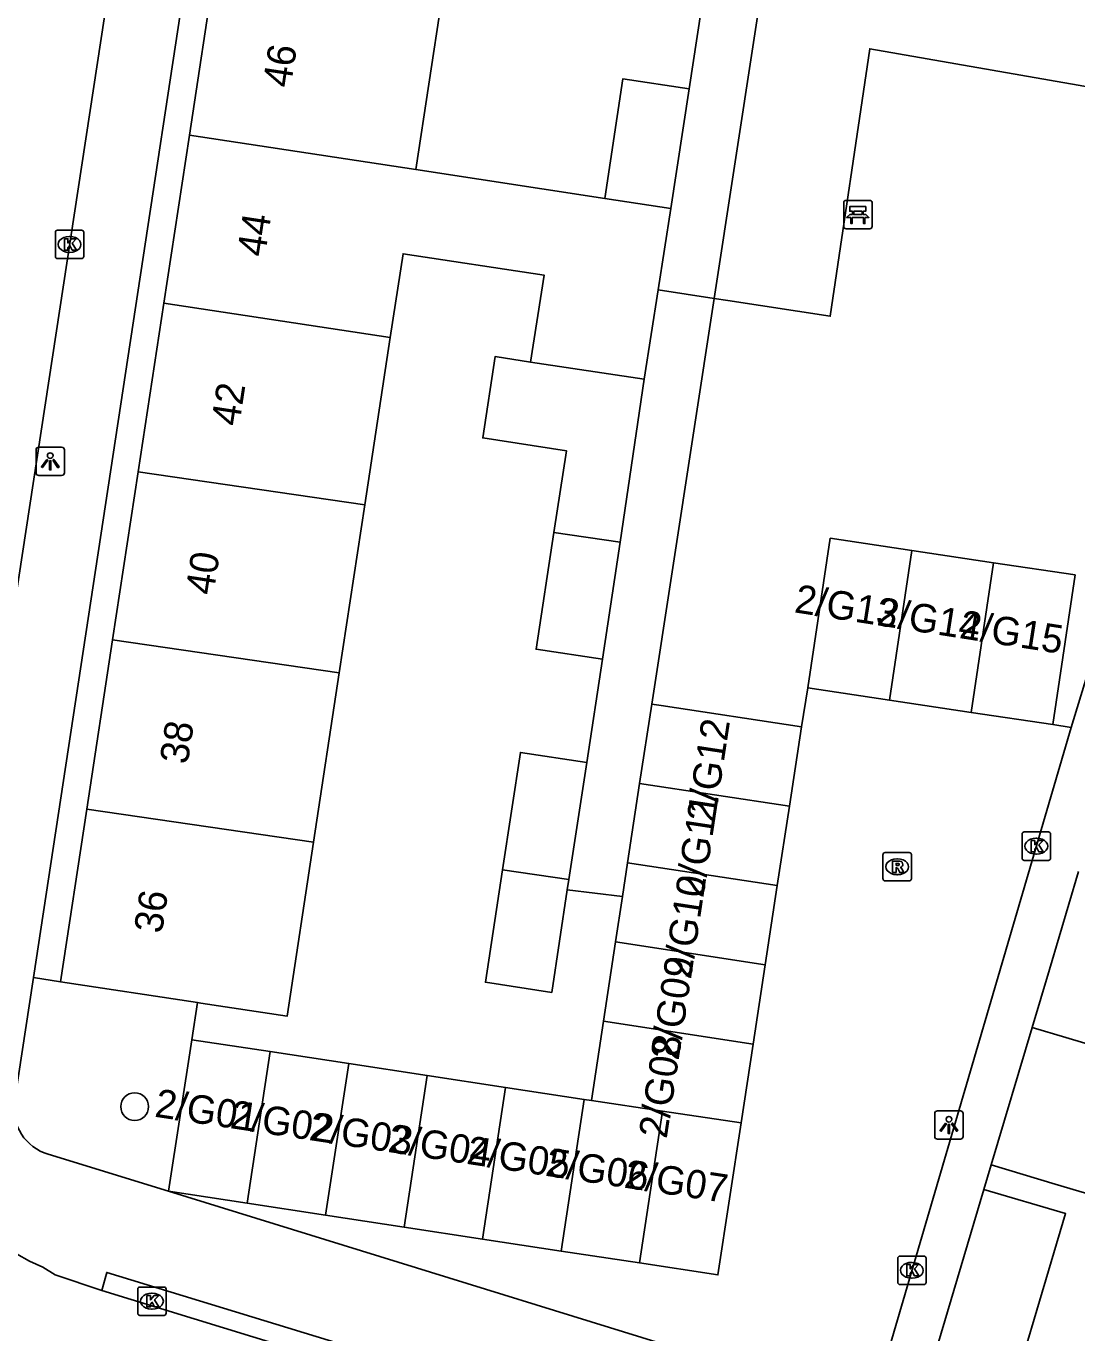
# Model space of a CAD drawing. Extents: x 161084 to 161928, y 385355 to 386522.
# Drawn here: x 161749.15 to 161786.17, y 385534.98 to 385581.01 of the extents above; entities that cross this region are included whole.
import ezdxf

# ---------------------------------------------------------------- set-up
doc = ezdxf.new("R2010")
doc.units = 0
for name, color, linetype in [('IMGEO_Bank', 7, 'Continuous'), ('IMGEO_Boom', 7, 'Continuous'), ('IMGEO_Groenvoorziening', 7, 'Continuous'), ('IMGEO_Kolk', 7, 'Continuous'), ('IMGEO_Lichtpunt', 7, 'Continuous'), ('IMGEO_Pand', 7, 'Continuous'), ('IMGEO_Pand_nummerreeks', 7, 'Continuous'), ('IMGEO_Rijbaan_lokaal_open', 7, 'Continuous'), ('IMGEO_Rioolput', 7, 'Continuous'), ('IMGEO_Voetpad_open', 7, 'Continuous')]:
    doc.layers.add(name, color=color, linetype=linetype)

msp = doc.modelspace()

# ---------------------------------------------------------------- linework, layer by layer
at = {"layer": 'IMGEO_Bank'}
for p, q in [((161777.952, 385573.949), (161777.952, 385574.79)), ((161777.952, 385574.79), (161777.952, 385573.949)), ((161778.027, 385574.874), (161778.868, 385574.874)), ((161778.868, 385574.874), (161778.027, 385574.874)), ((161778.952, 385574.799), (161778.952, 385573.958)), ((161778.952, 385573.958), (161778.952, 385574.799)), ((161778.649, 385574.272), (161778.256, 385574.272)), ((161778.261, 385574.38), (161778.261, 385574.486)), ((161778.305, 385574.486), (161778.305, 385574.38)), ((161778.593, 385574.492), (161778.311, 385574.492)), ((161778.311, 385574.374), (161778.593, 385574.374)), ((161778.599, 385574.38), (161778.599, 385574.486)), ((161778.643, 385574.486), (161778.643, 385574.38)), ((161778.877, 385573.874), (161778.036, 385573.874)), ((161778.036, 385573.874), (161778.877, 385573.874))]:
    msp.add_line(p, q, dxfattribs=at)
for points in [[(161778.255, 385574.492), (161778.169, 385574.492), (161778.169, 385574.653), (161778.732, 385574.653), (161778.732, 385574.492), (161778.649, 385574.492)], [(161778.199, 385574.272), (161778.057, 385574.272), (161778.169, 385574.374), (161778.255, 385574.374)], [(161778.249, 385574.265), (161778.249, 385574.058), (161778.206, 385574.058), (161778.206, 385574.265)], [(161778.649, 385574.374), (161778.732, 385574.374), (161778.844, 385574.272), (161778.705, 385574.272)], [(161778.699, 385574.265), (161778.699, 385574.058), (161778.655, 385574.058), (161778.655, 385574.265)]]:
    msp.add_lwpolyline(points, dxfattribs=at)
for centre, radius, start, end in [((161778.03, 385574.796), 0.0779, 92.4484, 184.2845), ((161778.03, 385574.796), 0.0779, 92.4484, 184.2845), ((161778.874, 385574.796), 0.0779, 2.4484, 94.2845), ((161778.874, 385574.796), 0.0779, 2.4484, 94.2845), ((161778.199, 385574.265), 0.00671, 2.8957, 87.1043), ((161778.256, 385574.265), 0.00671, 92.8957, 177.1043), ((161778.254, 385574.485), 0.00671, 2.8957, 87.1043), ((161778.254, 385574.381), 0.00671, 272.8957, 357.1043), ((161778.311, 385574.485), 0.00671, 92.8957, 177.1043), ((161778.311, 385574.381), 0.00671, 182.8957, 267.1043), ((161778.593, 385574.485), 0.00671, 2.8957, 87.1043), ((161778.593, 385574.381), 0.00671, 272.8957, 357.1043), ((161778.65, 385574.485), 0.00671, 92.8957, 177.1043), ((161778.65, 385574.381), 0.00671, 182.8957, 267.1043), ((161778.648, 385574.265), 0.00671, 2.8957, 87.1043), ((161778.705, 385574.265), 0.00671, 92.8957, 177.1043), ((161778.03, 385573.952), 0.0779, 182.4484, 274.2845), ((161778.03, 385573.952), 0.0779, 182.4484, 274.2845), ((161778.874, 385573.952), 0.0779, 272.4484, 4.2845), ((161778.874, 385573.952), 0.0779, 272.4484, 4.2845)]:
    msp.add_arc(centre, radius, start, end, dxfattribs=at)
at = {"layer": 'IMGEO_Boom'}
msp.add_circle((161752.976, 385542.947), 0.489, dxfattribs=at)
at = {"layer": 'IMGEO_Groenvoorziening'}
for points in [[(161750.362, 385547.348), (161749.416, 385547.492)], [(161755.185, 385546.613), (161754.986, 385545.305)]]:
    msp.add_lwpolyline(points, dxfattribs=at)
at = {"layer": 'IMGEO_Kolk'}
for p, q in [((161750.182, 385572.897), (161750.182, 385573.749)), ((161750.257, 385573.823), (161751.109, 385573.823)), ((161751.183, 385573.749), (161751.183, 385572.897)), ((161750.67, 385573.603), (161750.695, 385573.603)), ((161751.109, 385572.823), (161750.257, 385572.823)), ((161750.693, 385573.043), (161750.668, 385573.043)), ((161784.238, 385551.696), (161784.238, 385552.548)), ((161784.313, 385552.622), (161785.165, 385552.622)), ((161785.239, 385552.548), (161785.239, 385551.696)), ((161784.726, 385552.402), (161784.751, 385552.402)), ((161785.165, 385551.622), (161784.313, 385551.622)), ((161784.749, 385551.842), (161784.724, 385551.842)), ((161779.855, 385536.753), (161779.855, 385537.605)), ((161779.93, 385537.679), (161780.782, 385537.679)), ((161780.343, 385537.459), (161780.368, 385537.459)), ((161780.856, 385537.605), (161780.856, 385536.753)), ((161780.366, 385536.899), (161780.341, 385536.899)), ((161753.085, 385535.664), (161753.085, 385536.516)), ((161753.16, 385536.59), (161754.012, 385536.59)), ((161753.573, 385536.37), (161753.598, 385536.37)), ((161754.086, 385536.516), (161754.086, 385535.664)), ((161780.782, 385536.679), (161779.93, 385536.679)), ((161754.012, 385535.59), (161753.16, 385535.59)), ((161753.596, 385535.81), (161753.571, 385535.81))]:
    msp.add_line(p, q, dxfattribs=at)
for points in [[(161750.182, 385572.897), (161750.182, 385573.749)], [(161750.257, 385573.823), (161751.109, 385573.823)], [(161751.183, 385573.749), (161751.183, 385572.897)], [(161750.503, 385573.523), (161750.626, 385573.523), (161750.626, 385573.372), (161750.756, 385573.523), (161750.92, 385573.523), (161750.774, 385573.372), (161750.927, 385573.123), (161750.775, 385573.123), (161750.69, 385573.287), (161750.626, 385573.22), (161750.626, 385573.123), (161750.503, 385573.123), (161750.503, 385573.523)], [(161751.109, 385572.823), (161750.257, 385572.823)], [(161784.238, 385551.696), (161784.238, 385552.548)], [(161784.313, 385552.622), (161785.165, 385552.622)], [(161785.239, 385552.548), (161785.239, 385551.696)], [(161784.559, 385552.322), (161784.682, 385552.322), (161784.682, 385552.171), (161784.812, 385552.322), (161784.976, 385552.322), (161784.83, 385552.171), (161784.983, 385551.922), (161784.831, 385551.922), (161784.746, 385552.086), (161784.682, 385552.019), (161784.682, 385551.922), (161784.559, 385551.922), (161784.559, 385552.322)], [(161785.165, 385551.622), (161784.313, 385551.622)], [(161779.855, 385536.753), (161779.855, 385537.605)], [(161779.93, 385537.679), (161780.782, 385537.679)], [(161780.176, 385537.379), (161780.299, 385537.379), (161780.299, 385537.228), (161780.429, 385537.379), (161780.593, 385537.379), (161780.447, 385537.228), (161780.6, 385536.979), (161780.448, 385536.979), (161780.363, 385537.143), (161780.299, 385537.076), (161780.299, 385536.979), (161780.176, 385536.979), (161780.176, 385537.379)], [(161780.856, 385537.605), (161780.856, 385536.753)], [(161753.085, 385535.664), (161753.085, 385536.516)], [(161753.16, 385536.59), (161754.012, 385536.59)], [(161754.086, 385536.516), (161754.086, 385535.664)], [(161780.782, 385536.679), (161779.93, 385536.679)], [(161753.406, 385536.29), (161753.529, 385536.29), (161753.529, 385536.139), (161753.659, 385536.29), (161753.823, 385536.29), (161753.677, 385536.139), (161753.83, 385535.89), (161753.678, 385535.89), (161753.593, 385536.054), (161753.529, 385535.987), (161753.529, 385535.89), (161753.406, 385535.89), (161753.406, 385536.29)], [(161754.012, 385535.59), (161753.16, 385535.59)]]:
    msp.add_lwpolyline(points, dxfattribs=at)
for centre, start, end in [((161750.259, 385573.747), 91.552, 178.448), ((161750.259, 385573.747), 91.552, 178.448), ((161751.107, 385573.747), 1.552, 88.448), ((161751.107, 385573.747), 1.552, 88.448), ((161750.259, 385572.899), 181.552, 268.448), ((161750.259, 385572.899), 181.552, 268.448), ((161751.107, 385572.899), 271.552, 358.448), ((161751.107, 385572.899), 271.552, 358.448), ((161784.315, 385552.546), 91.552, 178.448), ((161784.315, 385552.546), 91.552, 178.448), ((161785.163, 385552.546), 1.552, 88.448), ((161785.163, 385552.546), 1.552, 88.448), ((161784.315, 385551.698), 181.552, 268.448), ((161784.315, 385551.698), 181.552, 268.448), ((161785.163, 385551.698), 271.552, 358.448), ((161785.163, 385551.698), 271.552, 358.448), ((161779.932, 385537.603), 91.552, 178.448), ((161779.932, 385537.603), 91.552, 178.448), ((161780.78, 385537.603), 1.552, 88.448), ((161780.78, 385537.603), 1.552, 88.448), ((161753.162, 385536.514), 91.552, 178.448), ((161753.162, 385536.514), 91.552, 178.448), ((161754.01, 385536.514), 1.552, 88.448), ((161754.01, 385536.514), 1.552, 88.448), ((161779.932, 385536.755), 181.552, 268.448), ((161779.932, 385536.755), 181.552, 268.448), ((161780.78, 385536.755), 271.552, 358.448), ((161780.78, 385536.755), 271.552, 358.448), ((161753.162, 385535.666), 181.552, 268.448), ((161753.162, 385535.666), 181.552, 268.448), ((161754.01, 385535.666), 271.552, 358.448), ((161754.01, 385535.666), 271.552, 358.448)]:
    msp.add_arc(centre, 0.0765, start, end, dxfattribs=at)
for centre, major_axis, ratio, start_param, end_param in [((161750.669, 385573.323), (-0.387, 0.002), 0.722429, 4.712389, 7.853982), ((161750.694, 385573.323), (-0.39, 0.002), 0.717154, 1.570796, 4.712389), ((161784.725, 385552.122), (-0.387, 0.002), 0.722429, 4.712389, 7.853982), ((161784.75, 385552.122), (-0.39, 0.002), 0.717154, 1.570796, 4.712389), ((161780.342, 385537.179), (-0.387, 0.002), 0.722429, 4.712389, 7.853982), ((161780.367, 385537.179), (-0.39, 0.002), 0.717154, 1.570796, 4.712389), ((161753.572, 385536.09), (-0.387, 0.002), 0.722429, 4.712389, 7.853982), ((161753.597, 385536.09), (-0.39, 0.002), 0.717154, 1.570796, 4.712389)]:
    msp.add_ellipse(centre, major_axis=major_axis, ratio=ratio, start_param=start_param, end_param=end_param, dxfattribs=at)
at = {"layer": 'IMGEO_Lichtpunt'}
for p, q in [((161749.503, 385566.084), (161749.503, 385565.277)), ((161749.503, 385566.084), (161749.503, 385565.277)), ((161750.405, 385566.179), (161749.597, 385566.179)), ((161750.405, 385566.179), (161749.597, 385566.179)), ((161750.499, 385565.277), (161750.499, 385566.084)), ((161750.499, 385565.277), (161750.499, 385566.084)), ((161749.597, 385565.183), (161750.405, 385565.183)), ((161749.597, 385565.183), (161750.405, 385565.183)), ((161781.162, 385542.702), (161781.162, 385541.895)), ((161781.162, 385542.702), (161781.162, 385541.895)), ((161782.064, 385542.797), (161781.256, 385542.797)), ((161782.064, 385542.797), (161781.256, 385542.797)), ((161782.158, 385541.895), (161782.158, 385542.702)), ((161782.158, 385541.895), (161782.158, 385542.702)), ((161781.256, 385541.801), (161782.064, 385541.801)), ((161781.256, 385541.801), (161782.064, 385541.801))]:
    msp.add_line(p, q, dxfattribs=at)
for points in [[(161749.877, 385565.748), (161749.916, 385565.72), (161749.728, 385565.458), (161749.69, 385565.485), (161749.877, 385565.748)], [(161749.979, 385565.7), (161750.026, 385565.7), (161750.026, 385565.378), (161749.979, 385565.378), (161749.979, 385565.7)], [(161750.089, 385565.72), (161750.127, 385565.747), (161750.314, 385565.485), (161750.275, 385565.457), (161750.089, 385565.72)], [(161781.536, 385542.366), (161781.575, 385542.338), (161781.387, 385542.076), (161781.349, 385542.103), (161781.536, 385542.366)], [(161781.748, 385542.338), (161781.786, 385542.365), (161781.973, 385542.103), (161781.934, 385542.075), (161781.748, 385542.338)], [(161781.638, 385542.318), (161781.685, 385542.318), (161781.685, 385541.996), (161781.638, 385541.996), (161781.638, 385542.318)]]:
    msp.add_lwpolyline(points, dxfattribs=at)
for centre in [(161750.002, 385565.882), (161781.661, 385542.5)]:
    msp.add_circle(centre, 0.0994, dxfattribs=at)
for centre, start, end in [((161749.597, 385566.084), 90, 180), ((161749.597, 385566.084), 90, 180), ((161750.405, 385566.084), 0, 90), ((161750.405, 385566.084), 0, 90), ((161749.597, 385565.277), 180, 270), ((161749.597, 385565.277), 180, 270), ((161750.405, 385565.277), 270, 0), ((161750.405, 385565.277), 270, 360), ((161781.256, 385542.702), 90, 180), ((161781.256, 385542.702), 90, 180), ((161782.064, 385542.702), 0, 90), ((161782.064, 385542.702), 0, 90), ((161781.256, 385541.895), 180, 270), ((161781.256, 385541.895), 180, 270), ((161782.064, 385541.895), 270, 0), ((161782.064, 385541.895), 270, 360)]:
    msp.add_arc(centre, 0.0946, start, end, dxfattribs=at)
at = {"layer": 'IMGEO_Pand'}
for points in [[(161755.814, 385583.147), (161754.905, 385577.176)], [(161762.883, 385575.96), (161763.801, 385581.981)], [(161769.534, 385574.946), (161770.175, 385579.16), (161772.508, 385578.805)], [(161772.508, 385578.805), (161771.867, 385574.591)], [(161754.003, 385571.254), (161754.905, 385577.176)], [(161754.905, 385577.176), (161762.883, 385575.96)], [(161762.883, 385575.96), (161769.534, 385574.946)], [(161769.534, 385574.946), (161771.867, 385574.591)], [(161771.867, 385574.591), (161771.416, 385571.723)], [(161766.923, 385569.179), (161767.403, 385572.238), (161762.432, 385572.994), (161761.982, 385570.039)], [(161771.416, 385571.723), (161770.92, 385568.571)], [(161754.003, 385571.254), (161753.098, 385565.313)], [(161761.982, 385570.039), (161754.003, 385571.254)], [(161761.982, 385570.039), (161761.084, 385564.146)], [(161766.923, 385569.179), (161765.674, 385569.369), (161765.238, 385566.504), (161768.183, 385566.056), (161767.744, 385563.173)], [(161770.92, 385568.571), (161766.923, 385569.179)], [(161770.08, 385562.831), (161770.92, 385568.571)], [(161753.098, 385565.313), (161752.196, 385559.391)], [(161753.098, 385565.313), (161761.084, 385564.146)], [(161761.084, 385564.146), (161760.182, 385558.225)], [(161769.453, 385558.706), (161767.119, 385559.061), (161767.744, 385563.173)], [(161767.744, 385563.173), (161770.08, 385562.831)], [(161770.08, 385562.831), (161769.453, 385558.706)], [(161780.356, 385562.539), (161777.481, 385562.97), (161776.691, 385557.696)], [(161779.566, 385557.266), (161780.356, 385562.539)], [(161783.23, 385562.109), (161780.356, 385562.539)], [(161783.23, 385562.109), (161782.44, 385556.835)], [(161785.315, 385556.405), (161786.105, 385561.678), (161783.23, 385562.109)], [(161752.196, 385559.391), (161751.288, 385553.43)], [(161760.182, 385558.225), (161752.196, 385559.391)], [(161760.182, 385558.225), (161759.274, 385552.264)], [(161776.691, 385557.696), (161779.566, 385557.266)], [(161770.765, 385554.333), (161771.19, 385557.126)], [(161776.463, 385556.324), (161771.52, 385557.076), (161771.19, 385557.126)], [(161779.566, 385557.266), (161782.44, 385556.835)], [(161782.44, 385556.835), (161785.315, 385556.405)], [(161776.038, 385553.531), (161776.463, 385556.324)], [(161765.938, 385551.291), (161766.566, 385555.423), (161768.899, 385555.068)], [(161768.899, 385555.068), (161768.273, 385550.95)], [(161770.765, 385554.333), (161770.34, 385551.54)], [(161776.038, 385553.531), (161770.765, 385554.333)], [(161751.288, 385553.43), (161750.362, 385547.348)], [(161751.288, 385553.43), (161759.274, 385552.264)], [(161775.613, 385550.738), (161776.038, 385553.531)], [(161759.274, 385552.264), (161758.344, 385546.132), (161755.305, 385546.595), (161755.185, 385546.613)], [(161768.217, 385550.582), (161767.668, 385546.971), (161765.335, 385547.326), (161765.938, 385551.291)], [(161768.273, 385550.95), (161765.938, 385551.291)], [(161770.34, 385551.54), (161770.159, 385550.354)], [(161770.34, 385551.54), (161775.613, 385550.738)], [(161786.228, 385551.232), (161785.198, 385547.778), (161784.588, 385545.731)], [(161768.273, 385550.95), (161768.217, 385550.582)], [(161775.188, 385547.945), (161775.613, 385550.738)], [(161769.915, 385548.748), (161770.159, 385550.354)], [(161769.49, 385545.955), (161769.915, 385548.748)], [(161769.915, 385548.748), (161775.188, 385547.945)], [(161774.763, 385545.152), (161775.188, 385547.945)], [(161755.185, 385546.613), (161750.362, 385547.348)], [(161769.065, 385543.162), (161769.49, 385545.955)], [(161774.763, 385545.152), (161769.49, 385545.955)], [(161784.588, 385545.731), (161783.145, 385540.894)], [(161784.588, 385545.731), (161785.783, 385545.376), (161789.477, 385544.279)], [(161754.173, 385539.962), (161754.986, 385545.305)], [(161754.986, 385545.305), (161757.75, 385544.884)], [(161774.34, 385542.372), (161774.763, 385545.152)], [(161757.75, 385544.884), (161756.938, 385539.541)], [(161757.75, 385544.884), (161760.515, 385544.463)], [(161760.515, 385544.463), (161759.702, 385539.121)], [(161760.515, 385544.463), (161763.279, 385544.042)], [(161789.477, 385544.279), (161791.331, 385543.729), (161790.669, 385541.508), (161789.888, 385538.886), (161785.408, 385540.22), (161783.145, 385540.894)], [(161762.467, 385538.7), (161763.279, 385544.042)], [(161763.279, 385544.042), (161766.044, 385543.622)], [(161766.044, 385543.622), (161765.231, 385538.28)], [(161766.044, 385543.622), (161768.809, 385543.201)], [(161767.996, 385537.859), (161768.809, 385543.201)], [(161768.809, 385543.201), (161769.065, 385543.162)], [(161769.065, 385543.162), (161771.574, 385542.786)], [(161770.76, 385537.439), (161771.574, 385542.786)], [(161770.76, 385537.439), (161773.525, 385537.018), (161774.34, 385542.372)], [(161771.574, 385542.786), (161774.34, 385542.372)], [(161754.173, 385539.962), (161756.938, 385539.541)], [(161782.887, 385540.031), (161780.461, 385531.837)], [(161782.887, 385540.031), (161785.767, 385539.179), (161783.34, 385530.984)], [(161756.938, 385539.541), (161759.702, 385539.121)], [(161759.702, 385539.121), (161762.467, 385538.7)], [(161762.467, 385538.7), (161765.231, 385538.28)], [(161765.231, 385538.28), (161767.996, 385537.859)], [(161767.996, 385537.859), (161770.76, 385537.439)]]:
    msp.add_lwpolyline(points, dxfattribs=at)
at = {"layer": 'IMGEO_Rijbaan_lokaal_open'}
for points in [[(161759.266, 385629.984), (161758.804, 385627.019), (161755.485, 385604.964), (161752.959, 385588.197), (161746.133, 385543.607)], [(161776.691, 385557.696), (161776.463, 385556.324)], [(161785.968, 385556.308), (161778.928, 385532.31)], [(161785.968, 385556.308), (161785.315, 385556.405)], [(161746.133, 385543.607), (161746.077, 385543.086), (161746.068, 385542.563), (161746.106, 385542.041), (161746.19, 385541.524), (161746.32, 385541.017), (161746.495, 385540.524), (161746.713, 385540.048), (161746.973, 385539.593), (161747.273, 385539.164), (161747.609, 385538.763), (161747.98, 385538.393), (161748.383, 385538.059), (161748.814, 385537.761), (161749.269, 385537.504), (161749.746, 385537.288), (161750.173, 385537.015), (161751.817, 385536.473)], [(161778.928, 385532.31), (161754.173, 385539.962)], [(161751.817, 385536.473), (161782.546, 385527.038)]]:
    msp.add_lwpolyline(points, dxfattribs=at)
at = {"layer": 'IMGEO_Rioolput'}
for p, q in [((161779.337, 385550.972), (161779.337, 385551.824)), ((161779.412, 385551.898), (161780.264, 385551.898)), ((161779.825, 385551.678), (161779.85, 385551.678)), ((161780.338, 385551.824), (161780.338, 385550.972)), ((161779.848, 385551.118), (161779.823, 385551.118)), ((161780.264, 385550.898), (161779.412, 385550.898))]:
    msp.add_line(p, q, dxfattribs=at)
for points in [[(161779.337, 385550.972), (161779.337, 385551.824)], [(161779.412, 385551.898), (161780.264, 385551.898)], [(161779.926, 385551.596), (161779.674, 385551.598), (161779.674, 385551.198)], [(161780.338, 385551.824), (161780.338, 385550.972)], [(161779.674, 385551.198), (161779.798, 385551.198), (161779.798, 385551.36), (161779.809, 385551.36)], [(161779.852, 385551.517), (161779.798, 385551.517), (161779.798, 385551.436)], [(161779.798, 385551.436), (161779.85, 385551.436)], [(161779.856, 385551.331), (161779.927, 385551.198), (161780.067, 385551.198), (161780.002, 385551.324)], [(161780.264, 385550.898), (161779.412, 385550.898)]]:
    msp.add_lwpolyline(points, dxfattribs=at)
for centre, radius, start, end in [((161779.414, 385551.822), 0.0765, 91.552, 178.448), ((161779.414, 385551.822), 0.0765, 91.552, 178.448), ((161779.925, 385551.486), 0.109, 350.3612, 89.416), ((161780.262, 385551.822), 0.0765, 1.552, 88.448), ((161780.262, 385551.822), 0.0765, 1.552, 88.448), ((161779.808, 385551.307), 0.0533, 26.0293, 88.6989), ((161779.834, 385551.625), 0.19, 274.7715, 282.9687), ((161779.858, 385551.421), 0.0964, 77.0061, 93.1865), ((161779.872, 385551.478), 0.0378, 276.6634, 79.6772), ((161779.923, 385551.486), 0.112, 277.5842, 350.9817), ((161779.907, 385551.271), 0.108, 29.5134, 73.7905), ((161779.414, 385550.974), 0.0765, 181.552, 268.448), ((161779.414, 385550.974), 0.0765, 181.552, 268.448), ((161780.262, 385550.974), 0.0765, 271.552, 358.448), ((161780.262, 385550.974), 0.0765, 271.552, 358.448)]:
    msp.add_arc(centre, radius, start, end, dxfattribs=at)
for centre, major_axis, ratio, start_param, end_param in [((161779.824, 385551.398), (-0.387, 0.002), 0.722429, 4.712389, 7.853982), ((161779.849, 385551.398), (-0.39, 0.002), 0.717154, 1.570796, 4.712389)]:
    msp.add_ellipse(centre, major_axis=major_axis, ratio=ratio, start_param=start_param, end_param=end_param, dxfattribs=at)
at = {"layer": 'IMGEO_Voetpad_open'}
for points in [[(161749.416, 385547.492), (161758.437, 385606.815), (161762.136, 385630.764)], [(161782.033, 385627.684), (161773.386, 385571.42)], [(161772.508, 385578.805), (161773.07, 385582.502)], [(161773.386, 385571.42), (161773.877, 385571.344), (161777.482, 385570.79), (161778.873, 385580.217), (161792.543, 385577.832)], [(161792.543, 385577.832), (161785.968, 385556.308)], [(161771.19, 385557.126), (161773.386, 385571.42)], [(161773.386, 385571.42), (161771.416, 385571.723)], [(161768.899, 385555.068), (161769.453, 385558.706)], [(161770.159, 385550.354), (161768.217, 385550.582)], [(161748.748, 385543.117), (161749.416, 385547.492)], [(161754.173, 385539.962), (161749.93, 385541.27), (161749.784, 385541.32), (161749.648, 385541.381), (161749.518, 385541.454), (161749.395, 385541.538), (161749.28, 385541.633), (161749.174, 385541.738), (161749.077, 385541.852), (161748.992, 385541.974), (161748.917, 385542.103), (161748.854, 385542.239), (161748.804, 385542.379), (161748.767, 385542.523), (161748.742, 385542.671), (161748.731, 385542.819), (161748.733, 385542.969), (161748.748, 385543.117)], [(161783.145, 385540.894), (161782.887, 385540.031)], [(161751.817, 385536.473), (161751.994, 385537.104), (161782.76, 385527.701), (161782.546, 385527.038)]]:
    msp.add_lwpolyline(points, dxfattribs=at)

# ---------------------------------------------------------------- texts
at = {"layer": 'IMGEO_Pand_nummerreeks'}
for s, rotation, p in [('46', 81.3409, (161758.472, 385578.814)), ('44', 81.3428, (161757.564, 385572.855)), ('42', 81.3409, (161756.656, 385566.892)), ('40', 81.3409, (161755.75, 385560.939)), ('2/G13', 351.142, (161776.184, 385560.364)), ('2/G14', 351.142, (161779.09, 385559.911)), ('2/G15', 351.142, (161781.996, 385559.458)), ('38', 81.3409, (161754.842, 385554.98)), ('2/G12', 81.3774, (161773.405, 385552.926)), ('2/G11', 81.3774, (161773.004, 385550.279)), ('2/G10', 81.3774, (161772.569, 385547.41)), ('36', 81.3409, (161753.934, 385549.017)), ('2/G09', 81.3774, (161772.135, 385544.551)), ('2/G08', 81.3774, (161771.717, 385541.795)), ('2/G01', 351.4121, (161753.65, 385542.594)), ('2/G02', 351.4121, (161756.308, 385542.193)), ('2/G03', 351.4121, (161759.088, 385541.773)), ('2/G04', 351.4121, (161761.862, 385541.354)), ('2/G05', 351.4121, (161764.636, 385540.935)), ('2/G06', 351.4121, (161767.41, 385540.516)), ('2/G07', 351.4121, (161770.184, 385540.097))]:
    msp.add_text(s, height=1, rotation=rotation, dxfattribs=at).set_placement(p)

doc.saveas('drawing.dxf')
